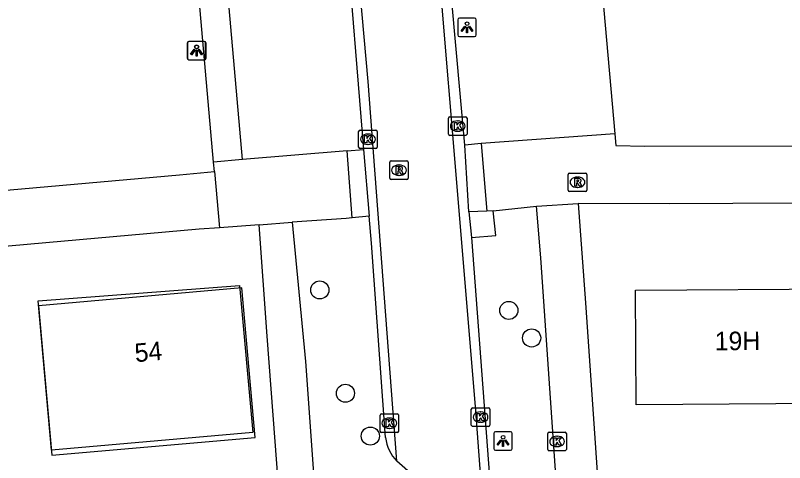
# Model space of a CAD drawing. Extents: x 162675 to 163482, y 379761 to 381227.
# Drawn here: x 163109.5 to 163151.01, y 380442.35 to 380466.52 of the extents above; entities that cross this region are included whole.
import ezdxf

# ---------------------------------------------------------------- set-up
doc = ezdxf.new("R2010")
doc.units = 0
for name, color, linetype in [('IMGEO_Berm_halfverhard', 7, 'Continuous'), ('IMGEO_Boom', 7, 'Continuous'), ('IMGEO_Kolk', 7, 'Continuous'), ('IMGEO_Lichtpunt', 7, 'Continuous'), ('IMGEO_Pand', 7, 'Continuous'), ('IMGEO_Pand_nummerreeks', 7, 'Continuous'), ('IMGEO_Pand_vergunning_verleend', 7, 'Continuous'), ('IMGEO_Parkeervlak_open', 7, 'Continuous'), ('IMGEO_Rijbaan_lokaal_gesloten', 7, 'Continuous'), ('IMGEO_Rijbaan_lokaal_open', 7, 'Continuous'), ('IMGEO_Rioolput', 7, 'Continuous'), ('IMGEO_Voetpad_open', 7, 'Continuous')]:
    doc.layers.add(name, color=color, linetype=linetype)

msp = doc.modelspace()

# ---------------------------------------------------------------- linework, layer by layer
at = {"layer": 'IMGEO_Berm_halfverhard'}
msp.add_lwpolyline([(163134.109, 380454.512), (163135.43, 380454.63), (163135.285, 380455.956)], dxfattribs=at)
at = {"layer": 'IMGEO_Boom'}
for centre in [(163125.929, 380451.685), (163136.13, 380450.578), (163137.362, 380449.09), (163127.312, 380446.102), (163128.656, 380443.79)]:
    msp.add_circle(centre, 0.489, dxfattribs=at)
at = {"layer": 'IMGEO_Kolk'}
for p, q in [((163132.875, 380460.109), (163132.875, 380460.961)), ((163132.95, 380461.035), (163133.802, 380461.035)), ((163133.876, 380460.961), (163133.876, 380460.109)), ((163133.363, 380460.815), (163133.388, 380460.815)), ((163128.024, 380459.399), (163128.024, 380460.251)), ((163128.099, 380460.325), (163128.951, 380460.325)), ((163128.512, 380460.105), (163128.537, 380460.105)), ((163129.025, 380460.251), (163129.025, 380459.399)), ((163133.386, 380460.255), (163133.361, 380460.255)), ((163133.802, 380460.035), (163132.95, 380460.035)), ((163128.951, 380459.325), (163128.099, 380459.325)), ((163128.535, 380459.545), (163128.51, 380459.545)), ((163134.104, 380444.386), (163134.104, 380445.238)), ((163134.179, 380445.312), (163135.031, 380445.312)), ((163135.105, 380445.238), (163135.105, 380444.386)), ((163129.184, 380444.06), (163129.184, 380444.912)), ((163129.259, 380444.986), (163130.111, 380444.986)), ((163129.672, 380444.766), (163129.697, 380444.766)), ((163130.185, 380444.912), (163130.185, 380444.06)), ((163134.592, 380445.092), (163134.617, 380445.092)), ((163135.031, 380444.312), (163134.179, 380444.312)), ((163134.615, 380444.532), (163134.59, 380444.532)), ((163130.111, 380443.986), (163129.259, 380443.986)), ((163129.695, 380444.206), (163129.67, 380444.206)), ((163138.237, 380443.073), (163138.237, 380443.925)), ((163138.312, 380443.999), (163139.164, 380443.999)), ((163139.238, 380443.925), (163139.238, 380443.073)), ((163138.725, 380443.779), (163138.75, 380443.779)), ((163138.748, 380443.219), (163138.723, 380443.219)), ((163139.164, 380442.999), (163138.312, 380442.999))]:
    msp.add_line(p, q, dxfattribs=at)
for points in [[(163132.875, 380460.109), (163132.875, 380460.961)], [(163132.95, 380461.035), (163133.802, 380461.035)], [(163133.876, 380460.961), (163133.876, 380460.109)], [(163133.196, 380460.735), (163133.319, 380460.735), (163133.319, 380460.584), (163133.449, 380460.735), (163133.613, 380460.735), (163133.467, 380460.584), (163133.62, 380460.335), (163133.468, 380460.335), (163133.383, 380460.499), (163133.319, 380460.432), (163133.319, 380460.335), (163133.196, 380460.335), (163133.196, 380460.735)], [(163128.024, 380459.399), (163128.024, 380460.251)], [(163128.099, 380460.325), (163128.951, 380460.325)], [(163129.025, 380460.251), (163129.025, 380459.399)], [(163128.345, 380460.025), (163128.468, 380460.025), (163128.468, 380459.874), (163128.598, 380460.025), (163128.762, 380460.025), (163128.616, 380459.874), (163128.769, 380459.625), (163128.617, 380459.625), (163128.532, 380459.789), (163128.468, 380459.722), (163128.468, 380459.625), (163128.345, 380459.625), (163128.345, 380460.025)], [(163133.802, 380460.035), (163132.95, 380460.035)], [(163128.951, 380459.325), (163128.099, 380459.325)], [(163134.104, 380444.386), (163134.104, 380445.238)], [(163134.179, 380445.312), (163135.031, 380445.312)], [(163135.105, 380445.238), (163135.105, 380444.386)], [(163129.184, 380444.06), (163129.184, 380444.912)], [(163129.259, 380444.986), (163130.111, 380444.986)], [(163130.185, 380444.912), (163130.185, 380444.06)], [(163134.425, 380445.012), (163134.548, 380445.012), (163134.548, 380444.861), (163134.678, 380445.012), (163134.842, 380445.012), (163134.696, 380444.861), (163134.849, 380444.612), (163134.697, 380444.612), (163134.612, 380444.776), (163134.548, 380444.709), (163134.548, 380444.612), (163134.425, 380444.612), (163134.425, 380445.012)], [(163129.505, 380444.686), (163129.628, 380444.686), (163129.628, 380444.535), (163129.758, 380444.686), (163129.922, 380444.686), (163129.776, 380444.535), (163129.929, 380444.286), (163129.777, 380444.286), (163129.692, 380444.45), (163129.628, 380444.383), (163129.628, 380444.286), (163129.505, 380444.286), (163129.505, 380444.686)], [(163135.031, 380444.312), (163134.179, 380444.312)], [(163130.111, 380443.986), (163129.259, 380443.986)], [(163138.237, 380443.073), (163138.237, 380443.925)], [(163138.312, 380443.999), (163139.164, 380443.999)], [(163139.238, 380443.925), (163139.238, 380443.073)], [(163138.558, 380443.699), (163138.681, 380443.699), (163138.681, 380443.548), (163138.811, 380443.699), (163138.975, 380443.699), (163138.829, 380443.548), (163138.982, 380443.299), (163138.83, 380443.299), (163138.745, 380443.463), (163138.681, 380443.396), (163138.681, 380443.299), (163138.558, 380443.299), (163138.558, 380443.699)], [(163139.164, 380442.999), (163138.312, 380442.999)]]:
    msp.add_lwpolyline(points, dxfattribs=at)
for centre, start, end in [((163132.952, 380460.959), 91.552, 178.448), ((163132.952, 380460.959), 91.552, 178.448), ((163133.8, 380460.959), 1.552, 88.448), ((163133.8, 380460.959), 1.552, 88.448), ((163128.101, 380460.249), 91.552, 178.448), ((163128.101, 380460.249), 91.552, 178.448), ((163128.949, 380460.249), 1.552, 88.448), ((163128.949, 380460.249), 1.552, 88.448), ((163132.952, 380460.111), 181.552, 268.448), ((163132.952, 380460.111), 181.552, 268.448), ((163133.8, 380460.111), 271.552, 358.448), ((163133.8, 380460.111), 271.552, 358.448), ((163128.101, 380459.401), 181.552, 268.448), ((163128.101, 380459.401), 181.552, 268.448), ((163128.949, 380459.401), 271.552, 358.448), ((163128.949, 380459.401), 271.552, 358.448), ((163134.181, 380445.236), 91.552, 178.448), ((163134.181, 380445.236), 91.552, 178.448), ((163135.029, 380445.236), 1.552, 88.448), ((163135.029, 380445.236), 1.552, 88.448), ((163129.261, 380444.91), 91.552, 178.448), ((163129.261, 380444.91), 91.552, 178.448), ((163130.109, 380444.91), 1.552, 88.448), ((163130.109, 380444.91), 1.552, 88.448), ((163134.181, 380444.388), 181.552, 268.448), ((163134.181, 380444.388), 181.552, 268.448), ((163135.029, 380444.388), 271.552, 358.448), ((163135.029, 380444.388), 271.552, 358.448), ((163129.261, 380444.062), 181.552, 268.448), ((163129.261, 380444.062), 181.552, 268.448), ((163130.109, 380444.062), 271.552, 358.448), ((163130.109, 380444.062), 271.552, 358.448), ((163138.314, 380443.923), 91.552, 178.448), ((163138.314, 380443.923), 91.552, 178.448), ((163139.162, 380443.923), 1.552, 88.448), ((163139.162, 380443.923), 1.552, 88.448), ((163138.314, 380443.075), 181.552, 268.448), ((163138.314, 380443.075), 181.552, 268.448), ((163139.162, 380443.075), 271.552, 358.448), ((163139.162, 380443.075), 271.552, 358.448)]:
    msp.add_arc(centre, 0.0765, start, end, dxfattribs=at)
for centre, major_axis, ratio, start_param, end_param in [((163133.362, 380460.535), (-0.387, 0.002), 0.722429, 4.712389, 7.853982), ((163133.387, 380460.535), (-0.39, 0.002), 0.717154, 1.570796, 4.712389), ((163128.511, 380459.825), (-0.387, 0.002), 0.722429, 4.712389, 7.853982), ((163128.536, 380459.825), (-0.39, 0.002), 0.717154, 1.570796, 4.712389), ((163129.671, 380444.486), (-0.387, 0.002), 0.722429, 4.712389, 7.853982), ((163129.696, 380444.486), (-0.39, 0.002), 0.717154, 1.570796, 4.712389), ((163134.591, 380444.812), (-0.387, 0.002), 0.722429, 4.712389, 7.853982), ((163134.616, 380444.812), (-0.39, 0.002), 0.717154, 1.570796, 4.712389), ((163138.724, 380443.499), (-0.387, 0.002), 0.722429, 4.712389, 7.853982), ((163138.749, 380443.499), (-0.39, 0.002), 0.717154, 1.570796, 4.712389)]:
    msp.add_ellipse(centre, major_axis=major_axis, ratio=ratio, start_param=start_param, end_param=end_param, dxfattribs=at)
at = {"layer": 'IMGEO_Lichtpunt'}
for p, q in [((163134.28, 380466.37), (163133.472, 380466.37)), ((163134.28, 380466.37), (163133.472, 380466.37)), ((163133.378, 380466.275), (163133.378, 380465.468)), ((163133.378, 380466.275), (163133.378, 380465.468)), ((163134.374, 380465.468), (163134.374, 380466.275)), ((163134.374, 380465.468), (163134.374, 380466.275)), ((163119.674, 380465.117), (163118.866, 380465.117)), ((163119.674, 380465.117), (163118.866, 380465.117)), ((163119.697, 380465.11), (163118.889, 380465.11)), ((163119.697, 380465.11), (163118.889, 380465.11)), ((163133.472, 380465.374), (163134.28, 380465.374)), ((163133.472, 380465.374), (163134.28, 380465.374)), ((163118.772, 380465.022), (163118.772, 380464.215)), ((163118.772, 380465.022), (163118.772, 380464.215)), ((163118.795, 380465.015), (163118.795, 380464.208)), ((163118.795, 380465.015), (163118.795, 380464.208)), ((163119.768, 380464.215), (163119.768, 380465.022)), ((163119.768, 380464.215), (163119.768, 380465.022)), ((163119.791, 380464.208), (163119.791, 380465.015)), ((163119.791, 380464.208), (163119.791, 380465.015)), ((163118.866, 380464.121), (163119.674, 380464.121)), ((163118.866, 380464.121), (163119.674, 380464.121)), ((163118.889, 380464.114), (163119.697, 380464.114)), ((163118.889, 380464.114), (163119.697, 380464.114)), ((163135.321, 380443.929), (163135.321, 380443.122)), ((163135.321, 380443.929), (163135.321, 380443.122)), ((163136.223, 380444.024), (163135.415, 380444.024)), ((163136.223, 380444.024), (163135.415, 380444.024)), ((163136.317, 380443.122), (163136.317, 380443.929)), ((163136.317, 380443.122), (163136.317, 380443.929)), ((163135.415, 380443.028), (163136.223, 380443.028)), ((163135.415, 380443.028), (163136.223, 380443.028))]:
    msp.add_line(p, q, dxfattribs=at)
for points in [[(163133.752, 380465.939), (163133.791, 380465.911), (163133.603, 380465.649), (163133.565, 380465.676), (163133.752, 380465.939)], [(163133.854, 380465.891), (163133.901, 380465.891), (163133.901, 380465.569), (163133.854, 380465.569), (163133.854, 380465.891)], [(163133.964, 380465.911), (163134.002, 380465.938), (163134.189, 380465.676), (163134.15, 380465.648), (163133.964, 380465.911)], [(163119.146, 380464.686), (163119.185, 380464.658), (163118.997, 380464.396), (163118.959, 380464.423), (163119.146, 380464.686)], [(163119.169, 380464.679), (163119.208, 380464.651), (163119.02, 380464.389), (163118.982, 380464.416), (163119.169, 380464.679)], [(163119.248, 380464.638), (163119.295, 380464.638), (163119.295, 380464.316), (163119.248, 380464.316), (163119.248, 380464.638)], [(163119.358, 380464.658), (163119.396, 380464.685), (163119.583, 380464.423), (163119.544, 380464.395), (163119.358, 380464.658)], [(163119.381, 380464.651), (163119.419, 380464.678), (163119.606, 380464.416), (163119.567, 380464.388), (163119.381, 380464.651)], [(163119.271, 380464.631), (163119.318, 380464.631), (163119.318, 380464.309), (163119.271, 380464.309), (163119.271, 380464.631)], [(163135.695, 380443.593), (163135.734, 380443.565), (163135.546, 380443.303), (163135.508, 380443.33), (163135.695, 380443.593)], [(163135.797, 380443.545), (163135.844, 380443.545), (163135.844, 380443.223), (163135.797, 380443.223), (163135.797, 380443.545)], [(163135.907, 380443.565), (163135.945, 380443.592), (163136.132, 380443.33), (163136.093, 380443.302), (163135.907, 380443.565)]]:
    msp.add_lwpolyline(points, dxfattribs=at)
for centre in [(163133.877, 380466.073), (163119.271, 380464.82), (163119.294, 380464.813), (163135.82, 380443.727)]:
    msp.add_circle(centre, 0.0994, dxfattribs=at)
for centre, start, end in [((163133.472, 380466.275), 90, 180), ((163133.472, 380466.275), 90, 180), ((163134.28, 380466.275), 0, 90), ((163134.28, 380466.275), 0, 90), ((163133.472, 380465.468), 180, 270), ((163133.472, 380465.468), 180, 270), ((163134.28, 380465.468), 270, 0), ((163134.28, 380465.468), 270, 360), ((163118.866, 380465.022), 90, 180), ((163118.866, 380465.022), 90, 180), ((163118.889, 380465.015), 90, 180), ((163118.889, 380465.015), 90, 180), ((163119.674, 380465.022), 0, 90), ((163119.674, 380465.022), 0, 90), ((163119.697, 380465.015), 0, 90), ((163119.697, 380465.015), 0, 90), ((163118.866, 380464.215), 180, 270), ((163118.866, 380464.215), 180, 270), ((163118.889, 380464.208), 180, 270), ((163118.889, 380464.208), 180, 270), ((163119.674, 380464.215), 270, 0), ((163119.674, 380464.215), 270, 360), ((163119.697, 380464.208), 270, 0), ((163119.697, 380464.208), 270, 360), ((163135.415, 380443.929), 90, 180), ((163135.415, 380443.929), 90, 180), ((163136.223, 380443.929), 0, 90), ((163136.223, 380443.929), 0, 90), ((163135.415, 380443.122), 180, 270), ((163135.415, 380443.122), 180, 270), ((163136.223, 380443.122), 270, 0), ((163136.223, 380443.122), 270, 360)]:
    msp.add_arc(centre, 0.0946, start, end, dxfattribs=at)
at = {"layer": 'IMGEO_Pand'}
for points in [[(163121.714, 380451.803), (163110.743, 380450.826), (163111.461, 380442.759), (163122.434, 380443.71), (163121.714, 380451.803)], [(163143, 380445.481), (163142.964, 380451.679), (163154.024, 380451.743), (163154.031, 380450.56), (163156.279, 380450.572), (163159.226, 380450.588), (163159.438, 380450.589), (163159.485, 380443.521), (163156.326, 380443.5), (163156.307, 380446.339), (163154.077, 380446.324), (163154.062, 380445.545), (163150.543, 380445.525), (163143, 380445.481)]]:
    msp.add_lwpolyline(points, dxfattribs=at)
at = {"layer": 'IMGEO_Pand_vergunning_verleend'}
msp.add_lwpolyline([(163110.734, 380451.092), (163121.604, 380451.916), (163122.306, 380443.988), (163111.447, 380443.027), (163110.734, 380451.092)], dxfattribs=at)
at = {"layer": 'IMGEO_Parkeervlak_open'}
msp.add_lwpolyline([(163140.67, 380473.493), (163141.858, 380460.128)], dxfattribs=at)
at = {"layer": 'IMGEO_Rijbaan_lokaal_gesloten'}
for points in [[(163135.387, 380431.171), (163134.334, 380445.392), (163131.43, 380480.159), (163128.125, 380515.07), (163123.524, 380563.677), (163117.274, 380629.188)], [(163130.094, 380442.435), (163128.535, 380462.939), (163127.457, 380475.027), (163123.634, 380515.495), (163119.159, 380562.859), (163115.178, 380604.321)], [(163131.714, 380441.004), (163130.094, 380442.435)]]:
    msp.add_lwpolyline(points, dxfattribs=at)
at = {"layer": 'IMGEO_Rijbaan_lokaal_open'}
for points in [[(163133.761, 380459.516), (163132.577, 380472.694)], [(163127.303, 380471.425), (163128.296, 380459.266)], [(163128.296, 380459.266), (163128.599, 380455.668)], [(163133.966, 380455.91), (163133.761, 380459.516)], [(163127.41, 380459.201), (163121.761, 380458.724)], [(163127.675, 380455.574), (163127.41, 380459.201)], [(163121.761, 380458.724), (163120.186, 380458.591)], [(163120.238, 380458.077), (163120.186, 380458.591)], [(163088.499, 380455.257), (163118.351, 380457.9), (163120.238, 380458.077)], [(163120.238, 380458.077), (163120.513, 380455.044)], [(163127.675, 380455.574), (163127.354, 380455.539), (163124.446, 380455.354)], [(163129.483, 380443.709), (163128.717, 380454.219), (163128.599, 380455.668)], [(163133.966, 380455.91), (163134.109, 380454.512)], [(163122.658, 380455.201), (163120.513, 380455.044)], [(163122.658, 380455.201), (163124.446, 380455.354)], [(163120.513, 380455.044), (163119.41, 380454.963), (163090.735, 380452.415), (163083.867, 380451.82)], [(163134.109, 380454.512), (163135.779, 380432.484)]]:
    msp.add_lwpolyline(points, dxfattribs=at)
msp.add_arc((163131.583, 380443.933), 2.112, 186.0814, 225.1626, dxfattribs=at)
at = {"layer": 'IMGEO_Rioolput'}
for p, q in [((163129.703, 380457.73), (163129.703, 380458.582)), ((163129.778, 380458.656), (163130.63, 380458.656)), ((163130.191, 380458.436), (163130.216, 380458.436)), ((163130.704, 380458.582), (163130.704, 380457.73)), ((163139.411, 380458.002), (163140.263, 380458.002)), ((163130.63, 380457.656), (163129.778, 380457.656)), ((163130.214, 380457.876), (163130.189, 380457.876)), ((163139.336, 380457.076), (163139.336, 380457.928)), ((163139.824, 380457.782), (163139.849, 380457.782)), ((163140.337, 380457.928), (163140.337, 380457.076)), ((163139.847, 380457.222), (163139.822, 380457.222)), ((163140.263, 380457.002), (163139.411, 380457.002))]:
    msp.add_line(p, q, dxfattribs=at)
for points in [[(163129.703, 380457.73), (163129.703, 380458.582)], [(163129.778, 380458.656), (163130.63, 380458.656)], [(163130.704, 380458.582), (163130.704, 380457.73)], [(163130.292, 380458.354), (163130.04, 380458.356), (163130.04, 380457.956)], [(163130.04, 380457.956), (163130.164, 380457.956), (163130.164, 380458.118), (163130.175, 380458.118)], [(163130.218, 380458.275), (163130.164, 380458.275), (163130.164, 380458.194)], [(163130.164, 380458.194), (163130.216, 380458.194)], [(163130.222, 380458.089), (163130.293, 380457.956), (163130.433, 380457.956), (163130.368, 380458.082)], [(163139.411, 380458.002), (163140.263, 380458.002)], [(163130.63, 380457.656), (163129.778, 380457.656)], [(163139.336, 380457.076), (163139.336, 380457.928)], [(163139.925, 380457.7), (163139.673, 380457.702), (163139.673, 380457.302)], [(163139.851, 380457.621), (163139.797, 380457.621), (163139.797, 380457.54)], [(163140.337, 380457.928), (163140.337, 380457.076)], [(163139.673, 380457.302), (163139.797, 380457.302), (163139.797, 380457.464), (163139.808, 380457.464)], [(163139.797, 380457.54), (163139.849, 380457.54)], [(163139.855, 380457.435), (163139.926, 380457.302), (163140.066, 380457.302), (163140.001, 380457.428)], [(163140.263, 380457.002), (163139.411, 380457.002)]]:
    msp.add_lwpolyline(points, dxfattribs=at)
for centre, radius, start, end in [((163129.78, 380458.58), 0.0765, 91.552, 178.448), ((163129.78, 380458.58), 0.0765, 91.552, 178.448), ((163130.628, 380458.58), 0.0765, 1.552, 88.448), ((163130.628, 380458.58), 0.0765, 1.552, 88.448), ((163130.174, 380458.065), 0.0533, 26.0293, 88.6989), ((163130.2, 380458.383), 0.19, 274.7715, 282.9687), ((163130.224, 380458.179), 0.0964, 77.0061, 93.1865), ((163130.238, 380458.236), 0.0378, 276.6634, 79.6772), ((163130.291, 380458.244), 0.109, 350.3612, 89.416), ((163130.289, 380458.244), 0.112, 277.5842, 350.9817), ((163130.273, 380458.029), 0.108, 29.5134, 73.7905), ((163139.413, 380457.926), 0.0765, 91.552, 178.448), ((163139.413, 380457.926), 0.0765, 91.552, 178.448), ((163140.261, 380457.926), 0.0765, 1.552, 88.448), ((163140.261, 380457.926), 0.0765, 1.552, 88.448), ((163129.78, 380457.732), 0.0765, 181.552, 268.448), ((163129.78, 380457.732), 0.0765, 181.552, 268.448), ((163130.628, 380457.732), 0.0765, 271.552, 358.448), ((163130.628, 380457.732), 0.0765, 271.552, 358.448), ((163139.857, 380457.525), 0.0964, 77.0061, 93.1865), ((163139.871, 380457.582), 0.0378, 276.6634, 79.6772), ((163139.924, 380457.59), 0.109, 350.3612, 89.416), ((163139.807, 380457.411), 0.0533, 26.0293, 88.6989), ((163139.833, 380457.729), 0.19, 274.7715, 282.9687), ((163139.922, 380457.59), 0.112, 277.5842, 350.9817), ((163139.906, 380457.375), 0.108, 29.5134, 73.7905), ((163139.413, 380457.078), 0.0765, 181.552, 268.448), ((163139.413, 380457.078), 0.0765, 181.552, 268.448), ((163140.261, 380457.078), 0.0765, 271.552, 358.448), ((163140.261, 380457.078), 0.0765, 271.552, 358.448)]:
    msp.add_arc(centre, radius, start, end, dxfattribs=at)
for centre, major_axis, ratio, start_param, end_param in [((163130.19, 380458.156), (-0.387, 0.002), 0.722429, 4.712389, 7.853982), ((163130.215, 380458.156), (-0.39, 0.002), 0.717154, 1.570796, 4.712389), ((163139.823, 380457.502), (-0.387, 0.002), 0.722429, 4.712389, 7.853982), ((163139.848, 380457.502), (-0.39, 0.002), 0.717154, 1.570796, 4.712389)]:
    msp.add_ellipse(centre, major_axis=major_axis, ratio=ratio, start_param=start_param, end_param=end_param, dxfattribs=at)
at = {"layer": 'IMGEO_Voetpad_open'}
for points in [[(163141.858, 380460.128), (163141.9, 380459.488), (163143.475, 380459.454), (163159.504, 380459.495), (163159.528, 380458.323), (163197.086, 380458.508), (163194.928, 380483.698), (163143.174, 380475.424), (163140.543, 380475.123), (163140.67, 380473.493)], [(163120.186, 380458.591), (163119.135, 380470.693)], [(163121.761, 380458.724), (163120.702, 380470.83)], [(163141.858, 380460.128), (163134.639, 380459.589)], [(163127.41, 380459.201), (163128.296, 380459.266)], [(163134.639, 380459.589), (163133.761, 380459.516)], [(163134.639, 380459.589), (163134.941, 380455.944)], [(163137.628, 380456.205), (163139.871, 380456.349)], [(163199.191, 380456.627), (163144.819, 380456.343), (163139.871, 380456.349)], [(163139.871, 380456.349), (163140.272, 380450.994), (163142.471, 380419.107), (163142.767, 380411.707)], [(163134.941, 380455.944), (163133.966, 380455.91)], [(163135.285, 380455.956), (163134.941, 380455.944)], [(163135.285, 380455.956), (163137.628, 380456.205)], [(163140.797, 380411.539), (163140.239, 380418.958), (163137.867, 380453.413), (163137.628, 380456.205)], [(163128.599, 380455.668), (163127.675, 380455.574)], [(163126.293, 380406.746), (163126.155, 380408.871), (163123.094, 380449.195), (163122.658, 380455.201)], [(163124.446, 380455.354), (163125.156, 380447.82), (163127.91, 380409.357), (163128.192, 380405.494)]]:
    msp.add_lwpolyline(points, dxfattribs=at)

# ---------------------------------------------------------------- texts
at = {"layer": 'IMGEO_Pand_nummerreeks'}
for s, rotation, p in [('19H', 0.3323, (163147.248, 380448.424)), ('54', 5.0879, (163115.981, 380447.779))]:
    msp.add_text(s, height=1, rotation=rotation, dxfattribs=at).set_placement(p)

doc.saveas('drawing.dxf')
